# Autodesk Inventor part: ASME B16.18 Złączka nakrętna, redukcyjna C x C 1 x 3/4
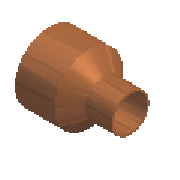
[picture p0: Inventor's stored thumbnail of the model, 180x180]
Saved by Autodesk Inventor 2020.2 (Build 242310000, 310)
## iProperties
NAME: PIPING: ASME B16.18 Reducing Coupling C x C
DATA: <meta><inlinegroups number="1" deflen="6.985"></inlinegroups><connections number="2"></connections><angles><a>3.14159265358979</a></angles></meta>
Manager: www.cadconsulting.pl
Company: Fabian Stasiak CAD Consulting
Created: 2014-02
Part Number: ASME B16.18 Złączka nakrętna, redukcyjna C x C 1 x 3/4
Material: Miedź, odlew
Description: Złączka nakrętna redukcyjna C x C odlewana ze stopu miedzi, lutowana na wcisk
Document SubType Name: Modeling
Standard: ASME B16.18
Designer: F.Stasiak
Standard Revision: 2001
Standards Organization: ANSI
Language: pl-PL
Size Designation: 1 x 3/4
Categories: <MemberInstance><Categories><Category DisplayName="Rury cienko- i grubościenne" InternalName="4347fa0f-2144-441d-94cd-e3e15c92b736" Mnemonic="TUBEANDPIPE"><Cate
Density: 1 g/cm^3
Appearance: Miedź - satynowa
Catalog Web Link: www.expertbooks.pl
IsCustomPart: 0
Author: F.Stasiak
Subject: Zbiór ćwiczeń. Autodesk Inventor 2020. Kurs Professional
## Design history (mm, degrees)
sketch "Sketch1"
  geometry: L1 (0, 0)-(-51.816, 0); L2 (0, 0)-(0, 14.326); L3 (0, 14.326)-(0, 16.104); L4 (0, 16.104)-(-23.114, 16.104); L5 (-23.114, 16.104)-(-32.766, 12.662); L6 (-32.766, 12.662)-(-51.816, 12.662); L7 (-51.816, 12.662)-(-51.816, 11.138); L8 (-51.816, 11.138)-(-32.766, 11.138); L9 (0, 14.326)-(-23.114, 14.326); L10 (-23.114, 14.326)-(-23.114, 13.31); L11 (-32.766, 11.138)-(-32.766, 10.122); L12 (-23.114, 14.326)-(-23.114, 16.104); L13 (-32.766, 11.138)-(-32.766, 12.662); L14 (-51.816, 0)-(-51.816, 11.138); L15 (-27.94, 14.383)-(-27.94, 12.605); L16 (-27.94, 12.605)-(-27.94, 0); A1 r 15.678 centre (-23.289, -2.368) between (-23.114, 13.31) and (-32.766, 10.122); 1 further point
  constraints: 32 end point, 8 parallel, 5 perpendicular, 3 point on circle, 1 centre point, 1 coincident, 1 collinear, 1 horizontal, 1 midpoint, 1 point on line
  dimensions: "d0" = 9.652 horizontal distance of L11.end L10.end (= N1); "d1" = 1.778 distance of L2.end L3.end (= R1); "d2" = 1.524 distance of L6.end L7.end (= R2); "d3" = 23.114 horizontal distance of L10.end L1.start (= G1); "d4" = 19.05 horizontal distance of L1.end L11.end (= G2); "d5" = 14.3256 distance of L1.start L2.end (= 0.5 x F1); "d6" = 11.1379 distance of L1.end L7.end (= 0.5 x F2); "d7" = 2.794 distance of L10.end L4.end (= T1); "d8" = 2.54 distance of L11.end L5.end (= T2); "d9" = 1.778 distance of L15.start L15.end (= R1)
revolve "Revolution1" sketch "Sketch1" stored, may be unused: angle "d10" = 90 deg
workaxis "Work Axis1"
workpoint "Work Point1"
workpoint "Work Point2"
workaxis "Work Axis2"
workpoint "Work Point3"
workaxis "Work Axis3"
workpoint "Work Point4"
body "Solid1"
other parameters: "N1" = 9.652 [user parameter; used in 1 equation term], "R1" = 1.778 [user parameter; used in 2 equation terms], "T1" = 2.794 [user parameter; used in 1 equation term], "F1" = 28.6512 [user parameter; used in 1 equation term], "G1" = 23.114 [user parameter; used in 1 equation term], "F2" = 22.2758 [user parameter; used in 1 equation term], "G2" = 19.05 [user parameter; used in 1 equation term], "R2" = 1.524 [user parameter; used in 1 equation term], "T2" = 2.54 [user parameter; used in 1 equation term], "Size_Designation" = 12.345 [user parameter]
